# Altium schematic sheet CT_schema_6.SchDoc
size 391 x 238 mm
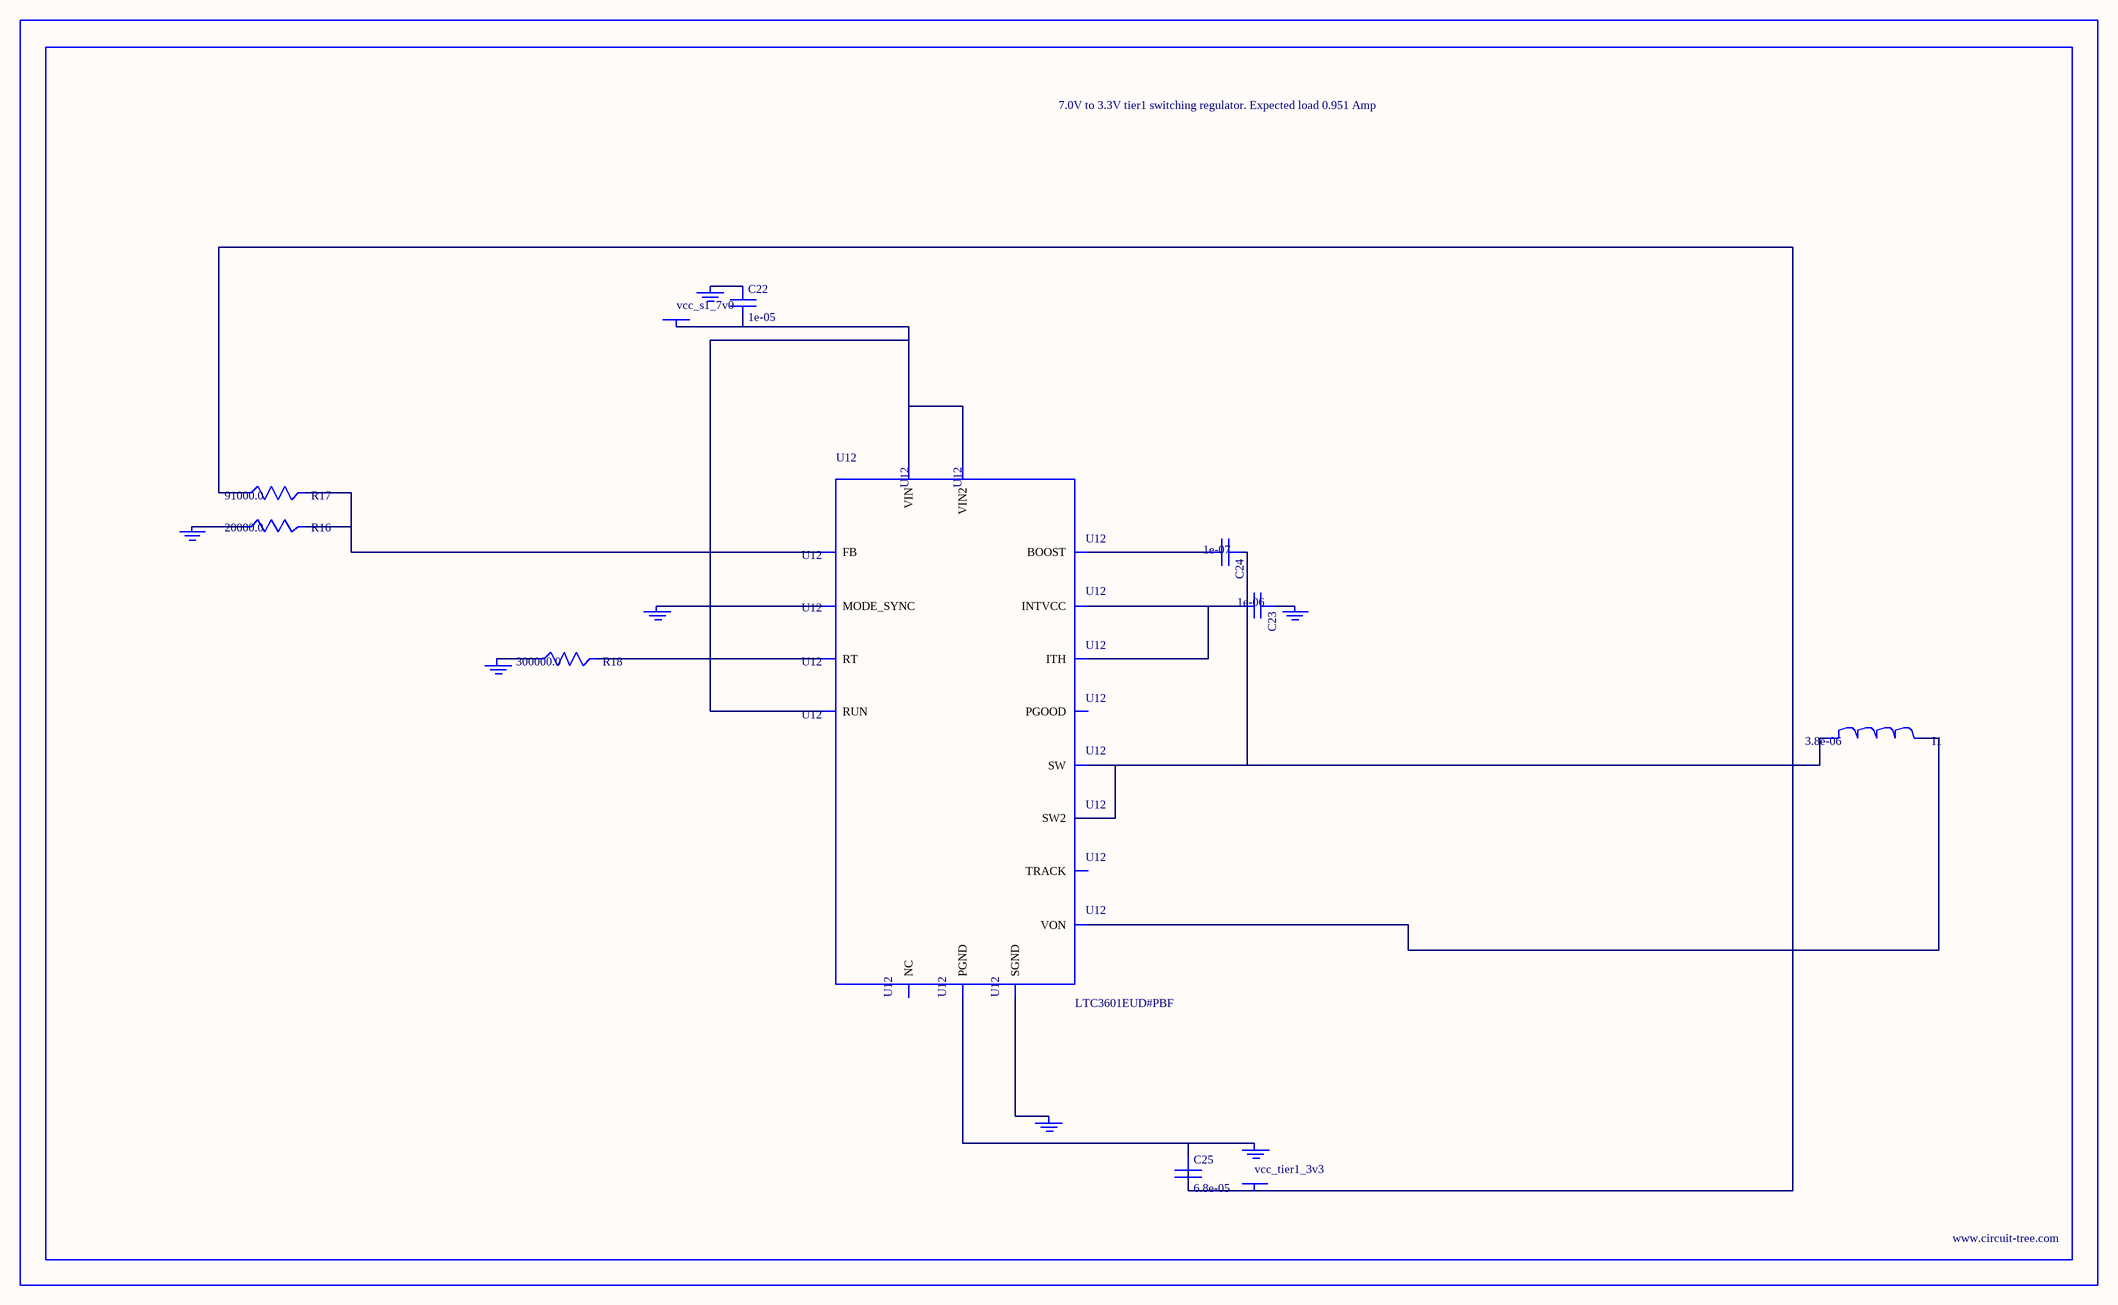
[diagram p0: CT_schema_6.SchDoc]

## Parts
BORDER5  (no value)
C22  1e-05  [C0805]
C23  1e-06  [C0603]
C24  1e-07  [C0402]
C25  6.8e-05  [2220]
GND_INSTANCE_5_0  (no value)
GND_INSTANCE_5_1  (no value)
GND_INSTANCE_5_2  (no value)
GND_INSTANCE_5_3  (no value)
GND_INSTANCE_5_4  (no value)
GND_INSTANCE_5_5  (no value)
GND_INSTANCE_5_6  (no value)
I1  3.8e-06  [DR1040]
POWER_INSTANCE_5_0  vcc_s1_7v0
POWER_INSTANCE_5_1  vcc_tier1_3v3
R16  20000.0  [R0603]
R17  91000.0  [R0603]
R18  300000.0  [R0603]
U12  LTC3601EUD#PBF  [QFN-16_EP]

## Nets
NetC22_1: C22.1 GND_INSTANCE_5_5.0(GND)
NetC22_2: C22.2 POWER_INSTANCE_5_0.0(PWR) U12.14(RUN) U12.15(VIN) U12.16(VIN2)
NetC23_1: C23.1 GND_INSTANCE_5_1.0(GND)
NetC23_2: C23.2 U12.7(INTVCC) U12.12(ITH)
NetC24_1: C24.1 I1.1 U12.3(SW) U12.4(SW2)
NetC24_2: C24.2 U12.6(BOOST)
NetC25_1: C25.1 GND_INSTANCE_5_6.0(GND) U12.17(PGND)
NetC25_2: C25.2 I1.2 POWER_INSTANCE_5_1.0(PWR) R17.1 U12.8(VON)
NetGND_INSTANCE_5_0_0: GND_INSTANCE_5_0.0(GND) U12.1(MODE_SYNC)
NetGND_INSTANCE_5_2_0: GND_INSTANCE_5_2.0(GND) U12.9(SGND)
NetGND_INSTANCE_5_3_0: GND_INSTANCE_5_3.0(GND) R18.1
NetGND_INSTANCE_5_4_0: GND_INSTANCE_5_4.0(GND) R16.1
NetR16_2: R16.2 R17.2 U12.11(FB)
NetR18_2: R18.2 U12.10(RT)

Not connected (* = marked no-connect by the designer): U12 2(PGOOD) 5(NC) 13(TRACK)

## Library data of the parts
BORDER5 = BORDER_PAGE5
C22 = C0805C106K8RACTU
C23 = C0603C105K3RACTU
C24 = C0402C104K3RACTU
C25 = C5750X5R1A686M
GND_INSTANCE_5_0-GND_INSTANCE_5_6 = GND
I1 = DR1040-3R8-R
POWER_INSTANCE_5_0 POWER_INSTANCE_5_1 = PWR
R16 = RC0603JR-0720KL
R17 = RC0603JR-0791KL
R18 = RC0603JR-07300KL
